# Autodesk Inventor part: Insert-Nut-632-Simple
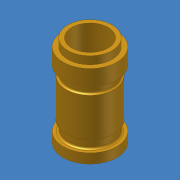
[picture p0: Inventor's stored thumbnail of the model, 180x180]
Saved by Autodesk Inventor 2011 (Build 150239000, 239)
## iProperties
Created: 2007-08
Part Number: Insert-Nut-632-Simple
Material: Brass, Soft Yellow
Document SubType Name: Modeling
Density: 8.47 g/cm^3
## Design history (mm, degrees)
feature "Base1"
body "Solid1"
